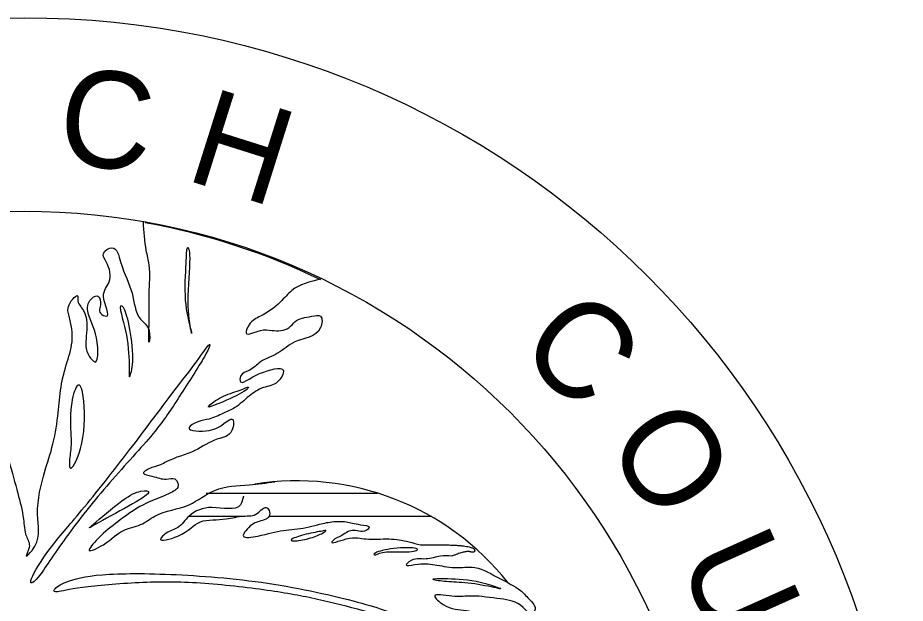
# Model space of a CAD drawing. Extents: x -0.7 to 16, y -0.9 to 9.7.
# Drawn here: x 9.0689 to 9.3534, y -0.2614 to -0.0737 of the extents above; entities that cross this region are included whole.
import ezdxf

# ---------------------------------------------------------------- set-up
doc = ezdxf.new("R2010")
doc.units = 0
doc.layers.add('Default', color=7, linetype='Continuous')

msp = doc.modelspace()

# ---------------------------------------------------------------- linework, layer by layer
at = {"layer": 'Default'}
for p, q in [((9.129340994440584, -0.2261339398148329), (9.184269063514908, -0.22613330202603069)), ((9.123834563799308, -0.2334531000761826), (9.141228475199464, -0.23344832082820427)), ((9.149467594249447, -0.23346653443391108), (9.20164932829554, -0.23345219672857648))]:
    msp.add_line(p, q, dxfattribs=at)
for radius in [0.28240568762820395, 0.2204114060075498]:
    msp.add_circle((9.070985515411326, -0.3561222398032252), radius, dxfattribs=at)
for centre, radius, start, end in [((9.070271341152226, -0.35626193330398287), 0.2204114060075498, 64.23515824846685, 79.6893776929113), ((9.158541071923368, -0.3082713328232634), 0.08611740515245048, 38.42000269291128, 99.14313602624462)]:
    msp.add_arc(centre, radius, start, end, dxfattribs=at)
for points in [[(8.99749953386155, -0.19684500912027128), (8.994757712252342, -0.1913385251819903), (8.99018031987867, -0.18676123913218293), (8.983776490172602, -0.1812822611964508), (8.980100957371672, -0.1794329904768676), (8.98011009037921, -0.1776021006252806), (8.983771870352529, -0.17762036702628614), (8.991086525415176, -0.17944201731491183), (9.00025038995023, -0.1821883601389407), (9.003907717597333, -0.18309918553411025), (9.007583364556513, -0.1849255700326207), (9.010325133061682, -0.1858547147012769), (9.011236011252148, -0.18677472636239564), (9.013973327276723, -0.18859642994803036), (9.012156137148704, -0.18584096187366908), (9.010320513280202, -0.18219282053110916), (9.007564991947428, -0.17943267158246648), (9.005743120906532, -0.1776155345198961), (9.006667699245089, -0.17578921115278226), (9.00849413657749, -0.176690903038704), (9.015804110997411, -0.17945088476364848), (9.023146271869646, -0.18493454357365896), (9.027719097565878, -0.1904272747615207), (9.030470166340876, -0.19407998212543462), (9.034118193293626, -0.19226724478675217), (9.032291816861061, -0.18676532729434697), (9.030460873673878, -0.18217885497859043), (9.027723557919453, -0.1803571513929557), (9.026794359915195, -0.17852158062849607), (9.028629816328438, -0.17761526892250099), (9.035042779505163, -0.18126335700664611), (9.041446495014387, -0.18676522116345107), (9.046930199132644, -0.1931779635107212), (9.049681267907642, -0.19683067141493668), (9.05335240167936, -0.20414983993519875), (9.054254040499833, -0.19774606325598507), (9.053343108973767, -0.19224871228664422), (9.051507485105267, -0.18860057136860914), (9.049685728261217, -0.18676054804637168), (9.0506103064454, -0.18493422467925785), (9.05426763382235, -0.1858450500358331), (9.058845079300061, -0.19499967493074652), (9.063427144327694, -0.20781619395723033), (9.06615526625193, -0.21606901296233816), (9.068920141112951, -0.22613006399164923), (9.070732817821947, -0.23437831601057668), (9.071666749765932, -0.23985289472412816), (9.072563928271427, -0.24351924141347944), (9.071657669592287, -0.24626112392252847), (9.073497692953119, -0.24443936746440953), (9.075310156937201, -0.23437826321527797), (9.077141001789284, -0.2206324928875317), (9.079887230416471, -0.21149151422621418), (9.081722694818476, -0.20140763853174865), (9.082633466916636, -0.19317297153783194), (9.08448257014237, -0.18494298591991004), (9.0863043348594, -0.1776054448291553), (9.085384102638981, -0.1693845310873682), (9.085379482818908, -0.16572263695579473), (9.088139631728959, -0.1629671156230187), (9.08813506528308, -0.16388256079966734), (9.089970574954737, -0.16755358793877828), (9.090890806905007, -0.17577450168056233), (9.091797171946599, -0.18218729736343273), (9.093618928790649, -0.18402732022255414), (9.094534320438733, -0.17945454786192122), (9.091792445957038, -0.16937072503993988), (9.091792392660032, -0.16479338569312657), (9.094547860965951, -0.16297619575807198), (9.095454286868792, -0.16478876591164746), (9.095458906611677, -0.16845066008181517), (9.097285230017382, -0.169375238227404), (9.09637886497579, -0.1629624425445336), (9.098209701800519, -0.15839423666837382), (9.097280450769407, -0.15198132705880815), (9.096378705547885, -0.14923042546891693), (9.099111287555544, -0.14741312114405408), (9.101857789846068, -0.15198127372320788), (9.10553810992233, -0.16204689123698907), (9.108266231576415, -0.1702997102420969), (9.111017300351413, -0.17395241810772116), (9.111021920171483, -0.17761431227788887), (9.11103100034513, -0.17120608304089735), (9.11103089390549, -0.16205140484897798), (9.111030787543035, -0.15289672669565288), (9.110115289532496, -0.1483148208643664), (9.109199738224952, -0.13915557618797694)], [(9.165958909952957, -0.15747342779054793), (9.156785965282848, -0.161135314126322), (9.153128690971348, -0.16480182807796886), (9.146720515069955, -0.16937008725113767), (9.14306780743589, -0.17212115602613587), (9.142138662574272, -0.17486292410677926), (9.146720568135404, -0.17394742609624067), (9.150382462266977, -0.17394280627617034), (9.155879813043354, -0.1730318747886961), (9.157719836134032, -0.17121011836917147), (9.16319886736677, -0.16938362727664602), (9.165945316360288, -0.16937444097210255), (9.165949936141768, -0.1730363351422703), (9.157710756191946, -0.17761834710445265), (9.152222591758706, -0.181275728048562), (9.146716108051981, -0.18401754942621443), (9.143063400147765, -0.18676861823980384), (9.140307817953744, -0.1886086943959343), (9.140321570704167, -0.19043969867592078), (9.143072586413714, -0.189515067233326), (9.146720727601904, -0.18767944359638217), (9.154048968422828, -0.18677764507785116), (9.152222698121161, -0.1904304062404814), (9.147636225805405, -0.19226134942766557), (9.143068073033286, -0.19500785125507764), (9.138495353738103, -0.19866979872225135), (9.13482432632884, -0.20050530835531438), (9.130237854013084, -0.20233625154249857), (9.126594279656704, -0.20325643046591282), (9.123838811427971, -0.2050736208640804), (9.130242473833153, -0.20599814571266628), (9.132993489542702, -0.20507351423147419), (9.135748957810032, -0.20325632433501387), (9.137561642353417, -0.20232701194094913), (9.13756626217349, -0.20598890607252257), (9.132998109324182, -0.20873540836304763), (9.125678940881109, -0.21240654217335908), (9.116505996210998, -0.2160684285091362), (9.11469342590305, -0.21697485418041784), (9.111942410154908, -0.21789948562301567), (9.109186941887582, -0.219716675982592), (9.111928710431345, -0.2206458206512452), (9.116524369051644, -0.2215613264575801), (9.119270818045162, -0.22155214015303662), (9.120172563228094, -0.22430304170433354), (9.119252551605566, -0.22521392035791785), (9.115604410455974, -0.22704954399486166), (9.109182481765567, -0.22978679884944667), (9.100961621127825, -0.23528436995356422), (9.094548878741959, -0.24076807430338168), (9.09180704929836, -0.2444391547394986), (9.096370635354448, -0.24260809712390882), (9.102778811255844, -0.2380398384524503), (9.108280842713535, -0.2361905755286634), (9.112848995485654, -0.2334440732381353), (9.123829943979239, -0.22979120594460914), (9.132069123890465, -0.22520919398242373), (9.143063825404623, -0.2233873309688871), (9.151307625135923, -0.22246721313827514)], [(9.141237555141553, -0.22704009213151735), (9.14030829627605, -0.22980474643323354), (9.131172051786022, -0.23069752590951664), (9.123834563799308, -0.2334531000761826), (9.12017728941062, -0.2371196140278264), (9.116506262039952, -0.2389551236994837), (9.114689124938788, -0.24077699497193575), (9.120186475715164, -0.23986606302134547), (9.1275102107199, -0.23527948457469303), (9.135731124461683, -0.23435925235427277), (9.141228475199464, -0.23344832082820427), (9.145810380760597, -0.23253282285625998), (9.148565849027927, -0.23071563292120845), (9.149476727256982, -0.23163564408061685), (9.149467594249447, -0.23346653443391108), (9.14581956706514, -0.23527927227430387), (9.14398399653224, -0.23620846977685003), (9.141242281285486, -0.23985666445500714), (9.145819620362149, -0.23985661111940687), (9.15404498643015, -0.23804382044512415), (9.161373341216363, -0.23711913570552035), (9.165039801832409, -0.23619907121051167), (9.169621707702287, -0.23528357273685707), (9.174199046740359, -0.23528351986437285), (9.178771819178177, -0.23619891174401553), (9.181513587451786, -0.23712805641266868), (9.180593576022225, -0.23803893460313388), (9.176016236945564, -0.23803898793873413), (9.172368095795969, -0.23987461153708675), (9.170532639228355, -0.24078092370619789), (9.169612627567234, -0.2416918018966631), (9.174194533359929, -0.2407763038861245), (9.180602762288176, -0.24078538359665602), (9.187926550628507, -0.24077614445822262), (9.194330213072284, -0.24170066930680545), (9.197987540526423, -0.2426114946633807), (9.201649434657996, -0.2426068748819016)], [(9.208062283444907, -0.24627784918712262), (9.204400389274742, -0.2462824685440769), (9.199818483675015, -0.24719796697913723), (9.19707214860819, -0.24718426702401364), (9.194321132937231, -0.24810889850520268), (9.193401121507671, -0.24901977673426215), (9.196147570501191, -0.24901059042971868), (9.20255579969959, -0.24901967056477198), (9.208982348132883, -0.24994430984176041), (9.215390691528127, -0.24993050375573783), (9.223611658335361, -0.2535876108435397), (9.23002450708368, -0.2572585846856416), (9.232780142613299, -0.2599958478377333), (9.234615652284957, -0.2636668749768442), (9.233695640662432, -0.26457775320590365), (9.230935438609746, -0.26275593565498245), (9.223625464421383, -0.25999595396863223), (9.214475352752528, -0.2590806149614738), (9.208067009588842, -0.25909442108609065), (9.202574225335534, -0.2590899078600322), (9.205306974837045, -0.2618270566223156), (9.212644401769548, -0.26367170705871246), (9.219043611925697, -0.26548879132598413), (9.2272873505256, -0.2691688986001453), (9.235522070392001, -0.2746570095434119), (9.241019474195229, -0.27832341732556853), (9.243770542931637, -0.281976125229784), (9.247414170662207, -0.2856332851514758), (9.24742792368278, -0.28746428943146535), (9.244672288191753, -0.2847270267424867), (9.236442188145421, -0.2829008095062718), (9.230029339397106, -0.2792298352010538), (9.22637657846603, -0.27740356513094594), (9.224541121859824, -0.2783098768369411), (9.231869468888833, -0.2865627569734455), (9.23644229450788, -0.2920554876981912), (9.2428369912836, -0.29936535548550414), (9.246503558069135, -0.3075999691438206), (9.24926369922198, -0.31402201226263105), (9.250179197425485, -0.3186039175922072), (9.250165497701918, -0.32135025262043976), (9.249250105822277, -0.325923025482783), (9.24741464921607, -0.3268293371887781), (9.245601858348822, -0.3186039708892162), (9.236442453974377, -0.3057875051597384), (9.230940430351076, -0.298459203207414), (9.221790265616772, -0.29296652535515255), (9.221785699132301, -0.2938819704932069), (9.225443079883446, -0.2993701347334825), (9.230954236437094, -0.3048675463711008), (9.233700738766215, -0.30943569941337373), (9.235513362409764, -0.3131066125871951), (9.235527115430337, -0.3149376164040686), (9.234597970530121, -0.317679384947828), (9.229114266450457, -0.3112666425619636), (9.223612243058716, -0.30393834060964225), (9.216302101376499, -0.2966239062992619), (9.210804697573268, -0.2929574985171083), (9.207151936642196, -0.2911312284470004), (9.208982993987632, -0.2956948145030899), (9.208983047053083, -0.30027215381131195), (9.211715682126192, -0.3030321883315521), (9.209889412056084, -0.30668494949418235), (9.208058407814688, -0.30669870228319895), (9.201645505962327, -0.2984503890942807), (9.194335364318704, -0.2911359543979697), (9.189739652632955, -0.28564310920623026), (9.184246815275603, -0.28106125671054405), (9.180589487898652, -0.2801504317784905), (9.17785228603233, -0.27830584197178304), (9.176941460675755, -0.2819631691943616), (9.179687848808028, -0.2865542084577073), (9.18150058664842, -0.2902022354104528), (9.183336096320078, -0.29387326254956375), (9.182429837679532, -0.29661514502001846), (9.180598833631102, -0.2966288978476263), (9.177852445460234, -0.29203785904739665), (9.172364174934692, -0.28654056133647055), (9.162293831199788, -0.27740430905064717), (9.157711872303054, -0.27374246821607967), (9.154054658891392, -0.2728087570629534), (9.151312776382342, -0.27190249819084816), (9.152214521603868, -0.2746533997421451), (9.156791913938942, -0.27923068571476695), (9.159547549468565, -0.28196794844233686), (9.161360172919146, -0.2856388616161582), (9.16136935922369, -0.2883853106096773), (9.156796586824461, -0.2874699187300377), (9.15128999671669, -0.281057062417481), (9.145810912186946, -0.2783062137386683), (9.137571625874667, -0.2737335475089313)], [(9.208062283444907, -0.24627784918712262), (9.204400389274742, -0.2462824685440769), (9.199818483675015, -0.24719796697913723), (9.19707214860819, -0.24718426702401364), (9.194321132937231, -0.24810889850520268), (9.193401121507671, -0.24901977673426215), (9.196147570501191, -0.24901059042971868), (9.20255579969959, -0.24901967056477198), (9.208982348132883, -0.24994430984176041), (9.215390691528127, -0.24993050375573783), (9.223611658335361, -0.2535876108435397), (9.23002450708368, -0.2572585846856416), (9.232780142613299, -0.2599958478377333), (9.234615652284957, -0.2636668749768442), (9.233695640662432, -0.26457775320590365), (9.230935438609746, -0.26275593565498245), (9.223625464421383, -0.25999595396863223), (9.214475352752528, -0.2590806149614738), (9.208067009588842, -0.25909442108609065), (9.202574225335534, -0.2590899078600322), (9.205306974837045, -0.2618270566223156), (9.212644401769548, -0.26367170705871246), (9.219043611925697, -0.26548879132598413), (9.2272873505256, -0.2691688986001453), (9.235522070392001, -0.2746570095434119), (9.241019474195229, -0.27832341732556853), (9.243770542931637, -0.281976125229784), (9.247414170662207, -0.2856332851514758), (9.24742792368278, -0.28746428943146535), (9.244672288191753, -0.2847270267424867), (9.236442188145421, -0.2829008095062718), (9.230029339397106, -0.2792298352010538), (9.22637657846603, -0.27740356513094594), (9.224541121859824, -0.2783098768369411), (9.231869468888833, -0.2865627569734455), (9.23644229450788, -0.2920554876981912), (9.2428369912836, -0.29936535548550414), (9.246503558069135, -0.3075999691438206), (9.24926369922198, -0.31402201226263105), (9.250179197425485, -0.3186039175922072), (9.250165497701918, -0.32135025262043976), (9.249250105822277, -0.325923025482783), (9.24741464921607, -0.3268293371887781), (9.245601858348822, -0.3186039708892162), (9.236442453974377, -0.3057875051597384), (9.230940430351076, -0.298459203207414), (9.221790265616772, -0.29296652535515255), (9.221785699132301, -0.2938819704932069), (9.225443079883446, -0.2993701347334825), (9.230954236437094, -0.3048675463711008), (9.233700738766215, -0.30943569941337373), (9.235513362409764, -0.3131066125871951), (9.235527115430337, -0.3149376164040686), (9.234597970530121, -0.317679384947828), (9.229114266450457, -0.3112666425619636), (9.223612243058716, -0.30393834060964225), (9.216302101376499, -0.2966239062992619), (9.210804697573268, -0.2929574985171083), (9.207151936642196, -0.2911312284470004), (9.208982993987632, -0.2956948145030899), (9.208983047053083, -0.30027215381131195), (9.211715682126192, -0.3030321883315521), (9.209889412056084, -0.30668494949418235), (9.208058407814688, -0.30669870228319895), (9.201645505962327, -0.2984503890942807), (9.194335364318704, -0.2911359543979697), (9.189739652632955, -0.28564310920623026), (9.184246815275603, -0.28106125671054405), (9.180589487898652, -0.2801504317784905), (9.17785228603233, -0.27830584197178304), (9.176941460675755, -0.2819631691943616), (9.179687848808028, -0.2865542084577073), (9.18150058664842, -0.2902022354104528), (9.183336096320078, -0.29387326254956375), (9.182429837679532, -0.29661514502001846), (9.180598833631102, -0.2966288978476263), (9.177852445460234, -0.29203785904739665), (9.172364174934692, -0.28654056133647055), (9.162293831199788, -0.27740430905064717), (9.157711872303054, -0.27374246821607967), (9.154054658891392, -0.2728087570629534), (9.151312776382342, -0.27190249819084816), (9.152214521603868, -0.2746533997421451), (9.156791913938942, -0.27923068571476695), (9.159547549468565, -0.28196794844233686), (9.161360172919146, -0.2856388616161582), (9.16136935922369, -0.2883853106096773), (9.156796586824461, -0.2874699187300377), (9.15128999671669, -0.281057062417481), (9.145810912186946, -0.2783062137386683), (9.137571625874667, -0.2737335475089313)]]:
    msp.add_spline(points, degree=3, dxfattribs=at)
for points, degree in [([(9.124451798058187, -0.1739507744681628), (9.124756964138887, -0.1754780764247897), (9.124744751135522, -0.1748677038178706), (9.122002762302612, -0.16480676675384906), (9.122918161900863, -0.15105642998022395), (9.122918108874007, -0.14647909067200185), (9.124762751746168, -0.14831922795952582), (9.12291375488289, -0.16570389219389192), (9.124146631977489, -0.17242347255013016), (9.124451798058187, -0.1739507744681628)], 3), ([(9.10492201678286, -0.18843980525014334), (9.10461687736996, -0.18920117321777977), (9.104604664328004, -0.18859080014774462), (9.104618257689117, -0.17668978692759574), (9.10094250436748, -0.16570872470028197), (9.102773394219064, -0.16571785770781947), (9.104622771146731, -0.17119700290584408), (9.106435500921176, -0.18402259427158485), (9.105227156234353, -0.187678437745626), (9.10492201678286, -0.18843980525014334)], 3), ([(9.073334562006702, -0.2534368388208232), (9.072573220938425, -0.2554203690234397), (9.07440411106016, -0.2554295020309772), (9.08356319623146, -0.2407819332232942), (9.098210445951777, -0.22247698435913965), (9.113764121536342, -0.20598460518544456), (9.120176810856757, -0.19592356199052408), (9.130255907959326, -0.18036511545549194), (9.131166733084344, -0.17670778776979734), (9.125678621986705, -0.18494250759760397), (9.118355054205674, -0.19408353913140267), (9.105520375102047, -0.21148206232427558), (9.08813129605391, -0.23345809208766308), (9.078972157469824, -0.24352832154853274), (9.07409590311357, -0.25145330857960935), (9.073334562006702, -0.2534368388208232)], 3), ([(9.085536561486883, -0.21528837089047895), (9.085689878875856, -0.2136107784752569), (9.086300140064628, -0.21056226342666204), (9.085389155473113, -0.20048757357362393), (9.087219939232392, -0.19134202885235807), (9.089970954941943, -0.19041739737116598), (9.090882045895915, -0.2096467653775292), (9.08538023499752, -0.22062781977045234), (9.085383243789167, -0.21696596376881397), (9.085536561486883, -0.21528837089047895)], 3), ([(9.130255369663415, -0.19806034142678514), (9.129645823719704, -0.19867142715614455), (9.130256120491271, -0.19867447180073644), (9.141241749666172, -0.19408327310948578), (9.143978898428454, -0.19135052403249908), (9.140307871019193, -0.19318603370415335), (9.133913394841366, -0.19500795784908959), (9.1308649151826, -0.19744925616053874), (9.130255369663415, -0.19806034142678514)], 3), ([(9.093168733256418, -0.23604271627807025), (9.09118446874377, -0.2377226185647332), (9.091797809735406, -0.23711536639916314), (9.105520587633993, -0.22979141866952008), (9.112844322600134, -0.22520484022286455), (9.108266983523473, -0.22520489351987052), (9.103703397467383, -0.22703595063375), (9.09515299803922, -0.2343628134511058), (9.093168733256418, -0.23604271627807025)], 3), ([(9.157560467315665, -0.241391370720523), (9.156492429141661, -0.24138985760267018), (9.155885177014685, -0.24077651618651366), (9.162279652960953, -0.23895459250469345), (9.167777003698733, -0.23804366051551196), (9.167777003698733, -0.23804366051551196), (9.166856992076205, -0.23895453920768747), (9.162293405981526, -0.24078559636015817), (9.158628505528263, -0.24139288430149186), (9.157560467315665, -0.241391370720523)], 3), ([(9.183648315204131, -0.24581276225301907), (9.183041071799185, -0.24596231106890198), (9.182433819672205, -0.24534897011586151), (9.188828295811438, -0.24352704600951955), (9.198898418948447, -0.2435315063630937), (9.195250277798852, -0.24536712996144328), (9.18607728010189, -0.24445167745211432), (9.18425555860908, -0.24566321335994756), (9.183648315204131, -0.24581276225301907)], 3), ([(9.201649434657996, -0.2426068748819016), (9.208973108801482, -0.24262052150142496), (9.215376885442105, -0.2435221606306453), (9.215390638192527, -0.24535316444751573), (9.212625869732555, -0.2444467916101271), (9.208062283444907, -0.24627784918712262)], 2), ([(9.08065600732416, -0.2569559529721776), (9.080199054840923, -0.25756398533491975), (9.080821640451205, -0.25816214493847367), (9.08721611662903, -0.2563402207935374), (9.108281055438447, -0.25449993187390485), (9.126590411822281, -0.25449971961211), (9.150378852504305, -0.2572503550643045), (9.165035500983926, -0.26000121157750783), (9.179687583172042, -0.2636675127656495), (9.194335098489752, -0.26824925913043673), (9.199814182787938, -0.2710001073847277), (9.202556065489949, -0.2719063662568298), (9.194321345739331, -0.2664182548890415), (9.182420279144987, -0.26182732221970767), (9.151307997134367, -0.25450858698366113), (9.118341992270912, -0.2517579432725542), (9.09362429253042, -0.25177196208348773), (9.083563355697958, -0.25451395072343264), (9.081112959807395, -0.2563479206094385), (9.08065600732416, -0.2569559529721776)], 3), ([(9.202101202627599, -0.2537435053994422), (9.201640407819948, -0.2535924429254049), (9.203471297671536, -0.25360157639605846), (9.214456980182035, -0.2535877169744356), (9.225447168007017, -0.2572586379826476), (9.22270528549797, -0.25635237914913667), (9.212644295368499, -0.2545170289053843), (9.206236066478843, -0.25450794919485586), (9.20256199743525, -0.25389456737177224), (9.202101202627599, -0.2537435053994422)], 3)]:
    msp.add_open_spline(points, degree=degree, dxfattribs=at)

# ---------------------------------------------------------------- texts
for s, height, rotation, p in [('C', 0.03099552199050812, 353.22679158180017, (9.080801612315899, -0.11994929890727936)), ('H', 0.030995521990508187, 342.4878499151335, (9.122016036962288, -0.1254417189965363)), ('C', 0.03099552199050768, 315.6404999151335, (9.228211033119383, -0.18035024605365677)), ('O', 0.03099552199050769, 304.9015582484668, (9.25657713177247, -0.21056486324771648)), ('U', 0.03099552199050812, 294.1626165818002, (9.280379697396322, -0.24718787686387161))]:
    msp.add_text(s, height=height, rotation=rotation, dxfattribs=at).set_placement(p)

doc.saveas('drawing.dxf')
